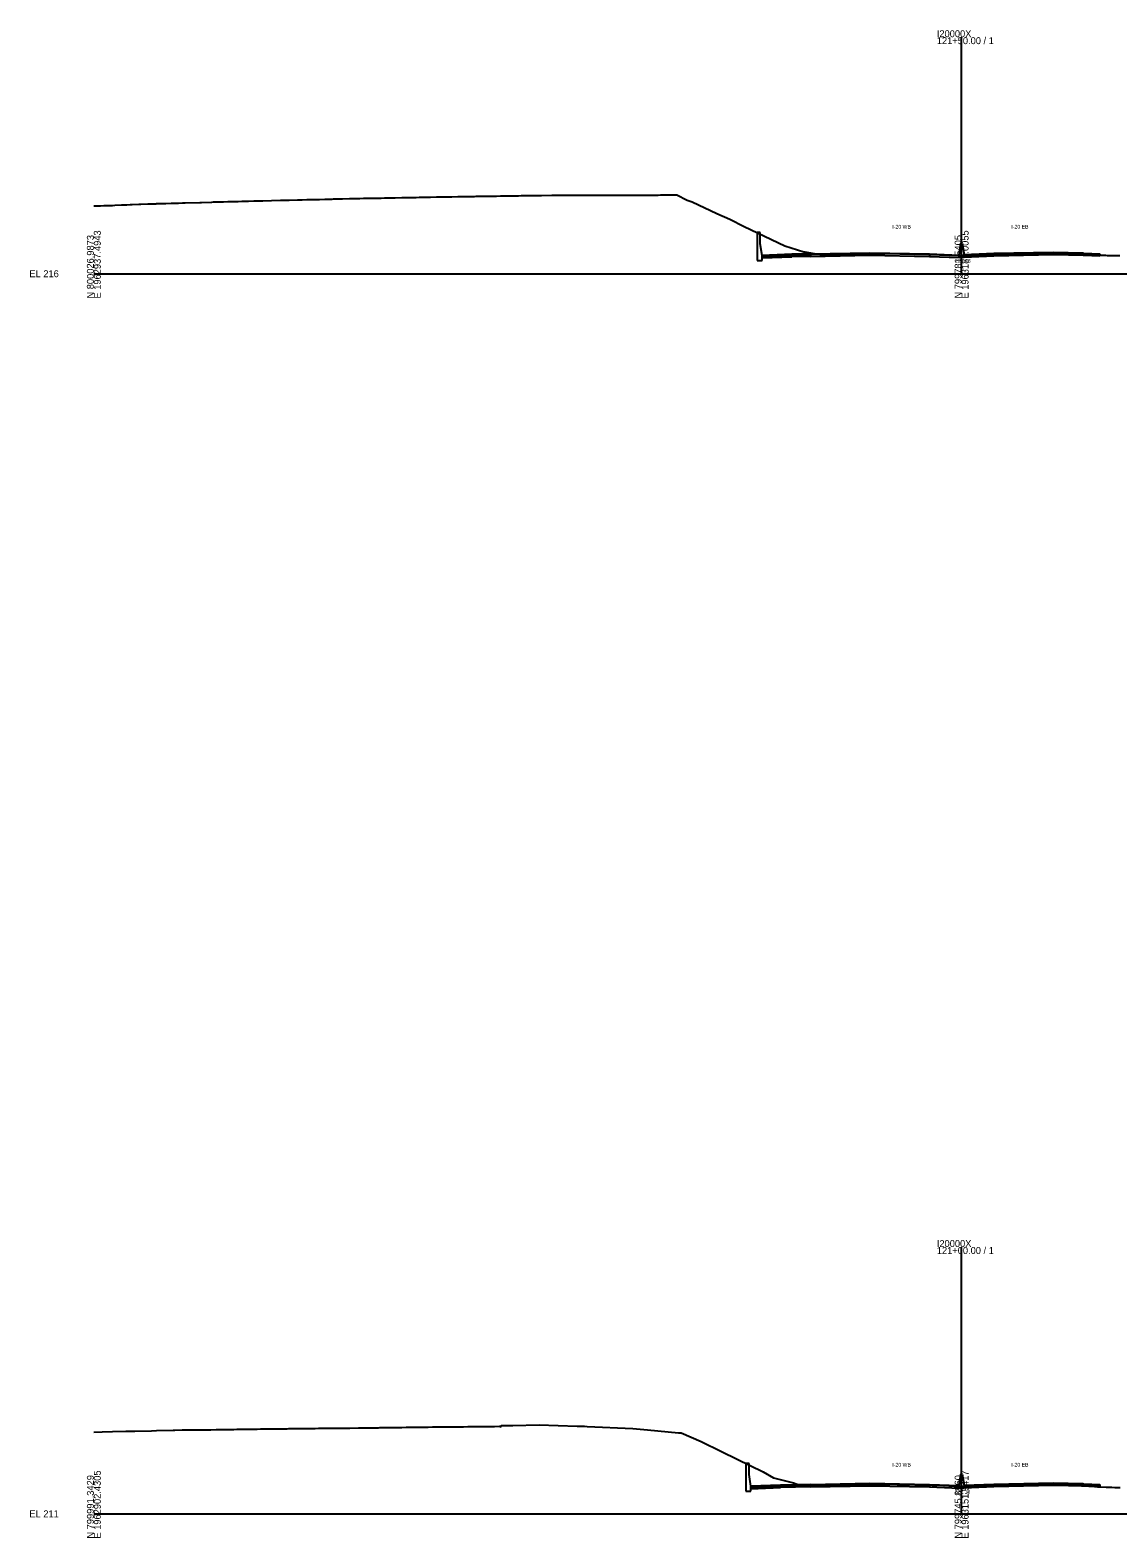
# Model space of a CAD drawing. Extents: x -4026 to 9638, y -10 to 19609.
# Drawn here: x 1974 to 2413, y 2490 to 3098 of the extents above; entities that cross this region are included whole.
import ezdxf

# ---------------------------------------------------------------- set-up
doc = ezdxf.new("R2010")
doc.units = 0
for name, color, linetype in [('Default', 7, 'Continuous'), ('RD_GPK_XS_Cell', 7, 'Continuous'), ('RD_TX_Misc1', 7, 'Continuous'), ('RD_XS_Base', 7, 'Continuous'), ('RD_XS_ExGround', 7, 'Continuous'), ('RD_XS_MedBWall', 7, 'Continuous'), ('RD_XS_Pave', 7, 'Continuous'), ('RD_XS_PaveOvlay', 7, 'Continuous'), ('RD_XS_TX_Elev_EX', 7, 'Continuous')]:
    doc.layers.add(name, color=color, linetype=linetype)

msp = doc.modelspace()

# ---------------------------------------------------------------- linework, layer by layer
at = {"layer": 'RD_GPK_XS_Cell'}
for p, q in [((2350, 3000), (2350, 3095.37)), ((2000, 3000), (2350, 3000)), ((2350, 3000), (2700, 3000)), ((2350, 2500), (2350, 2607.57)), ((2000, 2500), (2350, 2500)), ((2350, 2500), (2700, 2500))]:
    msp.add_line(p, q, dxfattribs=at)
at = {"layer": 'RD_XS_Base'}
for points in [[(2281.56, 3007.51), (2269.56, 3007.03)], [(2269.56, 3007.03), (2269.56, 3006.36)], [(2269.56, 3006.36), (2281.56, 3006.84)], [(2281.56, 3007.51), (2289, 3007.66)], [(2281.56, 3006.84), (2281.56, 3007.51)], [(2289, 3006.99), (2281.56, 3006.84)], [(2337, 3007.66), (2313, 3008.15), (2289, 3007.66)], [(2289, 3007.66), (2289, 3006.99)], [(2289, 3006.99), (2313, 3007.48), (2337, 3006.99)], [(2349, 3007.19), (2337, 3007.66)], [(2337, 3007.66), (2337, 3006.99)], [(2337, 3006.99), (2349, 3006.52)], [(2349, 3006.52), (2349, 3007.19)], [(2351, 3007.26), (2363, 3007.75)], [(2351, 3006.59), (2351, 3007.26)], [(2363, 3007.08), (2351, 3006.59)], [(2363, 3007.75), (2387, 3008.24), (2399, 3007.99)], [(2363, 3007.08), (2363, 3007.75)], [(2399, 3007.32), (2387, 3007.57), (2363, 3007.08)], [(2399, 3007.99), (2399.25, 3007.99)], [(2399, 3007.32), (2399, 3007.99)], [(2399.25, 3007.32), (2399, 3007.32)], [(2399.25, 3007.99), (2405.74, 3007.73)], [(2399.25, 3007.32), (2399.25, 3007.99)], [(2405.74, 3007.06), (2399.25, 3007.32)], [(2405.74, 3007.73), (2405.74, 3007.06)], [(2277, 2511.27), (2265, 2510.79)], [(2265, 2510.79), (2265, 2510.12)], [(2277, 2511.27), (2289, 2511.51)], [(2277, 2510.6), (2277, 2511.27)], [(2289, 2510.84), (2277, 2510.6)], [(2337, 2511.52), (2313, 2512), (2289, 2511.51)], [(2289, 2511.51), (2289, 2510.84)], [(2289, 2510.84), (2313, 2511.33), (2337, 2510.85)], [(2349, 2511.05), (2337, 2511.52)], [(2337, 2511.52), (2337, 2510.85)], [(2337, 2510.85), (2349, 2510.38)], [(2349, 2510.38), (2349, 2511.05)], [(2351, 2511.05), (2363, 2511.54)], [(2351, 2510.38), (2351, 2511.05)], [(2363, 2510.87), (2351, 2510.38)], [(2363, 2511.54), (2387, 2512.02), (2399, 2511.78)], [(2363, 2510.87), (2363, 2511.54)], [(2399, 2511.11), (2387, 2511.35), (2363, 2510.87)], [(2399, 2511.78), (2399.25, 2511.77)], [(2399, 2511.11), (2399, 2511.78)], [(2399.25, 2511.1), (2399, 2511.11)], [(2399.25, 2511.77), (2405.74, 2511.51)], [(2399.25, 2511.1), (2399.25, 2511.77)], [(2405.74, 2510.84), (2399.25, 2511.1)], [(2405.74, 2511.51), (2405.74, 2510.84)], [(2265, 2510.12), (2277, 2510.6)]]:
    msp.add_lwpolyline(points, dxfattribs=at)
at = {"layer": 'RD_XS_ExGround'}
for points in [[(2000, 3027.34), (2000.41, 3027.35), (2001.44, 3027.38), (2002.7, 3027.42), (2003.98, 3027.46), (2004.95, 3027.49), (2007.55, 3027.57), (2008.45, 3027.61), (2011.11, 3027.72), (2011.54, 3027.74), (2011.96, 3027.76), (2013.3, 3027.81), (2014.67, 3027.87), (2015.47, 3027.89), (2018.2, 3027.99), (2018.59, 3028.01), (2018.98, 3028.02), (2021.76, 3028.12), (2022.06, 3028.13), (2022.54, 3028.15), (2023.58, 3028.19), (2024.21, 3028.22), (2024.99, 3028.24), (2025.31, 3028.26), (2025.75, 3028.27), (2026.89, 3028.31), (2029.02, 3028.37), (2031.14, 3028.42), (2034.18, 3028.51), (2035.82, 3028.56), (2036.77, 3028.58), (2042.81, 3028.76), (2043.39, 3028.77), (2047.61, 3028.9), (2048.2, 3028.93), (2050.48, 3028.98), (2052.25, 3029.02), (2054.03, 3029.06), (2057.51, 3029.16), (2058.15, 3029.18), (2059.75, 3029.23), (2060.19, 3029.24), (2061.04, 3029.26), (2062.32, 3029.29), (2064.57, 3029.34), (2066.35, 3029.39), (2068.15, 3029.43), (2071.7, 3029.53), (2075.27, 3029.61), (2078.84, 3029.69), (2082.09, 3029.77), (2082.4, 3029.78), (2084, 3029.82), (2085.97, 3029.87), (2087.56, 3029.9), (2089.11, 3029.94), (2089.53, 3029.95), (2091.07, 3029.99), (2093.11, 3030.04), (2096.12, 3030.12), (2096.66, 3030.14), (2098.15, 3030.16), (2098.65, 3030.17), (2099.93, 3030.22), (2100.24, 3030.23), (2103.13, 3030.28), (2103.44, 3030.29), (2103.77, 3030.3), (2105.23, 3030.33), (2106.65, 3030.36), (2106.99, 3030.37), (2107.33, 3030.37), (2108.76, 3030.4), (2110.15, 3030.43), (2110.53, 3030.43), (2110.9, 3030.44), (2112.29, 3030.47), (2113.67, 3030.49), (2114.06, 3030.5), (2114.46, 3030.51), (2115.83, 3030.53), (2117.18, 3030.56), (2118.01, 3030.57), (2119.35, 3030.6), (2120.7, 3030.62), (2121.14, 3030.63), (2121.58, 3030.63), (2124.19, 3030.68), (2124.65, 3030.69), (2125.14, 3030.7), (2126.44, 3030.73), (2127.7, 3030.75), (2128.7, 3030.77), (2129.96, 3030.8), (2131.21, 3030.82), (2131.74, 3030.83), (2132.27, 3030.84), (2134.71, 3030.89), (2135.83, 3030.91), (2138.23, 3030.95), (2138.81, 3030.97), (2139.4, 3030.98), (2141.73, 3031.01), (2142.62, 3031.03), (2143.54, 3031.04), (2144.44, 3031.05), (2146.78, 3031.08), (2149.25, 3031.1), (2150.1, 3031.13), (2151.63, 3031.16), (2152.33, 3031.18), (2153.58, 3031.2), (2154.16, 3031.21), (2155.07, 3031.23), (2156.47, 3031.27), (2157.23, 3031.27), (2158.23, 3031.28), (2159.25, 3031.29), (2159.69, 3031.3), (2160.8, 3031.31), (2161.32, 3031.32), (2162.41, 3031.33), (2164.06, 3031.35), (2165.5, 3031.37), (2167.4, 3031.4), (2167.94, 3031.41), (2168.6, 3031.42), (2170.61, 3031.45), (2171.03, 3031.46), (2171.34, 3031.46), (2172.42, 3031.48), (2173.25, 3031.49), (2174.86, 3031.51), (2175.74, 3031.52), (2180.52, 3031.58), (2184.69, 3031.64), (2185.88, 3031.66), (2188.16, 3031.69), (2189.14, 3031.66), (2189.86, 3031.64), (2190.28, 3031.63), (2191.87, 3031.63), (2192.88, 3031.63), (2194.32, 3031.64), (2194.87, 3031.65), (2196.48, 3031.64), (2197.8, 3031.65), (2198.9, 3031.67), (2200.05, 3031.67), (2200.71, 3031.68), (2201.31, 3031.69), (2203.62, 3031.72), (2204.23, 3031.73), (2204.82, 3031.73), (2207.15, 3031.73), (2208.33, 3031.72), (2209.53, 3031.72), (2210.74, 3031.73), (2211.83, 3031.73), (2214.3, 3031.74), (2215.35, 3031.74), (2216.59, 3031.74), (2217.88, 3031.73), (2218.36, 3031.73), (2218.85, 3031.73), (2220.12, 3031.73), (2221.6, 3031.73), (2222.42, 3031.73), (2223.17, 3031.73), (2224.39, 3031.73), (2224.77, 3031.73), (2225.66, 3031.74), (2227.55, 3031.74), (2228.58, 3031.75), (2229.38, 3031.75), (2230.48, 3031.76), (2232.13, 3031.77), (2232.89, 3031.78), (2234.45, 3031.79), (2235.09, 3031.78), (2239.37, 3029.62), (2241.35, 3028.93), (2251.26, 3024.32), (2256.46, 3021.94), (2262.34, 3019.08), (2278.72, 3011.26), (2286.39, 3008.86), (2286.73, 3008.8), (2292.8, 3007.8), (2294.17, 3007.72), (2294.47, 3007.7), (2294.93, 3007.66), (2295.74, 3007.61), (2297.36, 3007.51), (2298.13, 3007.56), (2298.49, 3007.58), (2299.18, 3007.68), (2299.83, 3007.75), (2303.43, 3007.88), (2306.33, 3007.98), (2306.77, 3007.99), (2307.34, 3008.02), (2307.76, 3008.03), (2310.04, 3008.09), (2310.56, 3008.1), (2314.11, 3008.16), (2316.92, 3008.2), (2317.29, 3008.2), (2317.65, 3008.21), (2318.39, 3008.21), (2319.21, 3008.21), (2320.09, 3008.2), (2321.18, 3008.19), (2322.68, 3008.16), (2323.96, 3008.13), (2324.8, 3008.12), (2327.77, 3008.04), (2328.39, 3008.03), (2330.95, 3007.96), (2331.95, 3007.95), (2334.75, 3007.9), (2335.5, 3007.88), (2337.93, 3007.82), (2339.05, 3007.79), (2341.73, 3007.73), (2342.29, 3007.72), (2342.81, 3007.7), (2343.21, 3007.68), (2344.34, 3007.59), (2344.76, 3007.56), (2345.12, 3007.53), (2345.43, 3007.51), (2346.03, 3007.49), (2346.9, 3007.44), (2349.13, 3007.44), (2350, 3007.43), (2352.85, 3007.42), (2353.61, 3007.46), (2354.55, 3007.52), (2354.84, 3007.54), (2355.72, 3007.65), (2356.46, 3007.73), (2356.91, 3007.76), (2357.23, 3007.76), (2359.16, 3007.79), (2360.45, 3007.82), (2362.52, 3007.86), (2364, 3007.89), (2366.2, 3007.93), (2367.56, 3007.96), (2368.6, 3007.98), (2369.78, 3008.02), (2370.46, 3008.04), (2371.11, 3008.06), (2372.97, 3008.11), (2374.7, 3008.16), (2376.64, 3008.19), (2378.3, 3008.22), (2379.52, 3008.24), (2380.61, 3008.22), (2381.09, 3008.21), (2381.85, 3008.2), (2383.84, 3008.16), (2385.42, 3008.12), (2387.24, 3008.07), (2388.97, 3008.02), (2390.6, 3007.97), (2392.51, 3007.88), (2393.3, 3007.84), (2394.19, 3007.82), (2395.18, 3007.8), (2396.08, 3007.77), (2397.79, 3007.71), (2399.65, 3007.65), (2401.1, 3007.6), (2403.23, 3007.53), (2403.96, 3007.5), (2404.71, 3007.47), (2405.77, 3007.43), (2406.77, 3007.43), (2408.05, 3007.42), (2408.66, 3007.41), (2410.35, 3007.39), (2411.69, 3007.37), (2413.87, 3007.34)], [(2000, 2532.95), (2003.34, 2533.03), (2007.51, 2533.13), (2012.96, 2533.26), (2016.56, 2533.34), (2023.25, 2533.5), (2025.26, 2533.55), (2032.06, 2533.72), (2032.63, 2533.73), (2035.63, 2533.8), (2037.33, 2533.81), (2037.75, 2533.81), (2038.81, 2533.82), (2039.43, 2533.83), (2040.03, 2533.84), (2040.62, 2533.84), (2042.28, 2533.86), (2043.6, 2533.88), (2044.74, 2533.89), (2045.83, 2533.9), (2047.13, 2533.92), (2049.39, 2533.95), (2050, 2533.96), (2050.62, 2533.96), (2052.95, 2533.99), (2054.11, 2534.01), (2055.31, 2534.03), (2056.52, 2534.05), (2057.65, 2534.06), (2060.11, 2534.1), (2060.63, 2534.1), (2061.14, 2534.11), (2063.67, 2534.14), (2064.62, 2534.16), (2065.93, 2534.18), (2067.22, 2534.2), (2067.82, 2534.2), (2068.73, 2534.22), (2070.25, 2534.23), (2071.01, 2534.25), (2073.21, 2534.27), (2074.37, 2534.28), (2074.76, 2534.29), (2075.15, 2534.29), (2075.72, 2534.3), (2077.91, 2534.32), (2078.68, 2534.33), (2080.06, 2534.35), (2081.46, 2534.36), (2081.84, 2534.36), (2082.2, 2534.37), (2085.04, 2534.39), (2085.37, 2534.4), (2085.69, 2534.4), (2088.59, 2534.44), (2088.9, 2534.44), (2089.2, 2534.45), (2090.67, 2534.47), (2092.69, 2534.48), (2094.21, 2534.5), (2095.71, 2534.51), (2096.24, 2534.51), (2097.74, 2534.53), (2099.25, 2534.54), (2099.75, 2534.55), (2101.27, 2534.57), (2103.25, 2534.59), (2106.75, 2534.63), (2110.27, 2534.67), (2113.77, 2534.71), (2114.86, 2534.73), (2115.41, 2534.74), (2117.28, 2534.76), (2118.96, 2534.79), (2120.77, 2534.82), (2122.49, 2534.84), (2124.27, 2534.86), (2126.02, 2534.89), (2127.79, 2534.91), (2131.36, 2534.96), (2133.09, 2534.98), (2134.89, 2535), (2136.63, 2535.02), (2138.49, 2535.04), (2142.01, 2535.07), (2143.69, 2535.08), (2145.31, 2535.09), (2145.66, 2535.1), (2149.16, 2535.12), (2150.78, 2535.14), (2152.35, 2535.16), (2152.78, 2535.17), (2154.23, 2535.17), (2155.87, 2535.2), (2156.28, 2535.2), (2157.64, 2535.2), (2158.87, 2535.2), (2160.18, 2535.24), (2161.57, 2535.26), (2163.45, 2535.28), (2163.83, 2535.15), (2164.15, 2535.1), (2164.47, 2535.55), (2166.35, 2535.6), (2168.96, 2535.66), (2179.63, 2535.86), (2194.89, 2535.39), (2197.96, 2535.27), (2198.95, 2535.21), (2217.35, 2534.33), (2223.35, 2533.88), (2235.85, 2532.68), (2236.86, 2532.59), (2244.92, 2529.1), (2253.11, 2525.18), (2259.46, 2522.02), (2269.97, 2516.9), (2274.09, 2514.47), (2282.16, 2512.47), (2285.1, 2511.47), (2286.71, 2511.21), (2292.7, 2511.32), (2294.75, 2511.15), (2298.08, 2511.22), (2298.25, 2511.34), (2298.53, 2511.34), (2299.29, 2511.45), (2299.61, 2511.47), (2301.07, 2511.53), (2302.54, 2511.59), (2303.1, 2511.61), (2304.62, 2511.65), (2306.07, 2511.7), (2306.8, 2511.73), (2307.51, 2511.76), (2309.94, 2511.82), (2313.7, 2511.9), (2316.73, 2511.94), (2317.15, 2511.94), (2319.39, 2511.95), (2320.64, 2511.94), (2322.28, 2511.91), (2324.06, 2511.87), (2325.74, 2511.83), (2327.46, 2511.79), (2327.91, 2511.78), (2331.11, 2511.71), (2334.63, 2511.66), (2336.43, 2511.63), (2338.13, 2511.58), (2338.73, 2511.57), (2341.67, 2511.51), (2342.83, 2511.48), (2344.8, 2511.31), (2345.13, 2511.27), (2346.99, 2511.19), (2347.41, 2511.2), (2347.92, 2511.2), (2350, 2511.16), (2351.23, 2511.13), (2351.76, 2511.12), (2352.22, 2511.11), (2352.57, 2511.12), (2354.69, 2511.21), (2355.01, 2511.23), (2355.95, 2511.4), (2357.16, 2511.47), (2359.61, 2511.5), (2361.17, 2511.53), (2362.57, 2511.56), (2363.09, 2511.57), (2366.23, 2511.62), (2366.64, 2511.63), (2370.2, 2511.72), (2371.69, 2511.77), (2373.77, 2511.82), (2375.26, 2511.86), (2376.73, 2511.89), (2377.43, 2511.9), (2379.19, 2511.94), (2379.51, 2511.95), (2380.45, 2511.94), (2380.97, 2511.93), (2382.34, 2511.91), (2384.51, 2511.86), (2387.7, 2511.77), (2388.04, 2511.76), (2390.83, 2511.67), (2391.43, 2511.64), (2391.86, 2511.62), (2392.53, 2511.58), (2394.3, 2511.52), (2394.72, 2511.51), (2395.16, 2511.48), (2396.52, 2511.42), (2397.85, 2511.35), (2398.31, 2511.33), (2398.78, 2511.3), (2400.08, 2511.22), (2401.35, 2511.14), (2402.34, 2511.09), (2404.82, 2510.93), (2405.87, 2510.87), (2408.31, 2510.78), (2408.85, 2510.77), (2409.4, 2510.75), (2410.62, 2510.7), (2411.78, 2510.66), (2412.38, 2510.64), (2413.01, 2510.62), (2413.96, 2510.59)]]:
    msp.add_lwpolyline(points, dxfattribs=at)
at = {"layer": 'RD_XS_MedBWall'}
for points in [[(2268.81, 3016.59), (2267.56, 3016.59)], [(2267.56, 3016.59), (2267.56, 3005.37)], [(2268.81, 3012.04), (2268.81, 3016.59)], [(2269.56, 3007.37), (2268.81, 3012.04)], [(2349, 3007.52), (2349.75, 3012.26), (2350.25, 3012.26), (2351, 3007.59)], [(2267.56, 3005.37), (2269.56, 3005.37)], [(2269.56, 3005.37), (2269.56, 3007.37)], [(2349, 3006.52), (2349, 3007.52)], [(2351, 3006.52), (2349, 3006.52)], [(2351, 3007.59), (2351, 3006.52)], [(2264.25, 2520.29), (2263, 2520.29)], [(2263, 2520.29), (2263, 2509.13)], [(2264.25, 2515.8), (2264.25, 2520.29)], [(2265, 2511.13), (2264.25, 2515.8)], [(2265, 2509.13), (2265, 2511.13)], [(2349, 2511.37), (2349.75, 2516.04), (2350.25, 2516.04), (2351, 2511.37)], [(2349, 2510.37), (2349, 2511.37)], [(2351, 2511.37), (2351, 2510.37)], [(2263, 2509.13), (2265, 2509.13)], [(2351, 2510.37), (2349, 2510.37)]]:
    msp.add_lwpolyline(points, dxfattribs=at)
at = {"layer": 'RD_XS_Pave'}
for points in [[(2281.56, 3007.68), (2269.56, 3007.2)], [(2269.56, 3007.03), (2281.56, 3007.51)], [(2269.56, 3007.2), (2269.56, 3007.03)], [(2281.56, 3007.68), (2289, 3007.83)], [(2281.56, 3007.51), (2281.56, 3007.68)], [(2289, 3007.66), (2281.56, 3007.51)], [(2289, 3007.83), (2313, 3008.31), (2337, 3007.83)], [(2337, 3007.66), (2313, 3008.15), (2289, 3007.66)], [(2289, 3007.83), (2289, 3007.66)], [(2337, 3007.83), (2337, 3007.66)], [(2337, 3007.83), (2349, 3007.36)], [(2349, 3007.19), (2337, 3007.66)], [(2349, 3007.36), (2349, 3007.19)], [(2363, 3007.92), (2351, 3007.43)], [(2351, 3007.26), (2363, 3007.75)], [(2351, 3007.43), (2351, 3007.26)], [(2399, 3008.16), (2387, 3008.4), (2363, 3007.92)], [(2363, 3007.75), (2387, 3008.24), (2399, 3007.99)], [(2363, 3007.92), (2363, 3007.75)], [(2399, 3008.16), (2399.25, 3008.16)], [(2399, 3007.99), (2399, 3008.16)], [(2399.25, 3007.99), (2399, 3007.99)], [(2399.25, 3008.16), (2399.25, 3007.99)], [(2399.25, 3008.16), (2405.74, 3007.9)], [(2405.74, 3007.73), (2399.25, 3007.99)], [(2405.74, 3007.9), (2405.74, 3007.73)], [(2277, 2511.44), (2265, 2510.96)], [(2265, 2510.79), (2277, 2511.27)], [(2265, 2510.96), (2265, 2510.79)], [(2277, 2511.44), (2289, 2511.68)], [(2289, 2511.51), (2277, 2511.27)], [(2277, 2511.27), (2277, 2511.44)], [(2289, 2511.68), (2313, 2512.17), (2337, 2511.69)], [(2337, 2511.52), (2313, 2512), (2289, 2511.51)], [(2289, 2511.68), (2289, 2511.51)], [(2337, 2511.69), (2337, 2511.52)], [(2337, 2511.69), (2349, 2511.22)], [(2349, 2511.05), (2337, 2511.52)], [(2349, 2511.22), (2349, 2511.05)], [(2363, 2511.71), (2351, 2511.22)], [(2351, 2511.05), (2363, 2511.54)], [(2351, 2511.22), (2351, 2511.05)], [(2399, 2511.95), (2387, 2512.19), (2363, 2511.71)], [(2363, 2511.54), (2387, 2512.02), (2399, 2511.78)], [(2363, 2511.71), (2363, 2511.54)], [(2399, 2511.95), (2399.25, 2511.94)], [(2399, 2511.78), (2399, 2511.95)], [(2399.25, 2511.77), (2399, 2511.78)], [(2399.25, 2511.94), (2399.25, 2511.77)], [(2399.25, 2511.94), (2405.74, 2511.68)], [(2405.74, 2511.51), (2399.25, 2511.77)], [(2405.74, 2511.68), (2405.74, 2511.51)]]:
    msp.add_lwpolyline(points, dxfattribs=at)
at = {"layer": 'RD_XS_PaveOvlay'}
for points in [[(2281.56, 3007.85), (2269.56, 3007.37)], [(2269.56, 3007.2), (2281.56, 3007.68)], [(2269.56, 3007.37), (2269.56, 3007.2)], [(2289, 3008), (2281.56, 3007.85)], [(2281.56, 3007.85), (2281.56, 3007.68)], [(2281.56, 3007.68), (2289, 3007.83)], [(2289, 3008), (2313, 3008.48), (2337, 3008)], [(2337, 3007.83), (2313, 3008.31), (2289, 3007.83)], [(2289, 3007.83), (2289, 3008)], [(2337, 3008), (2337, 3007.83)], [(2337, 3008), (2349, 3007.52)], [(2349, 3007.36), (2337, 3007.83)], [(2349, 3007.52), (2349, 3007.36)], [(2363, 3008.09), (2351, 3007.59)], [(2351, 3007.43), (2363, 3007.92)], [(2351, 3007.59), (2351, 3007.43)], [(2399, 3008.33), (2387, 3008.57), (2363, 3008.09)], [(2363, 3007.92), (2387, 3008.4), (2399, 3008.16)], [(2363, 3008.09), (2363, 3007.92)], [(2399, 3008.16), (2399, 3008.33)], [(2399, 3008.33), (2399.25, 3008.32)], [(2399.25, 3008.16), (2399, 3008.16)], [(2399.25, 3008.32), (2405.74, 3008.06)], [(2399.25, 3008.16), (2399.25, 3008.32)], [(2405.74, 3007.9), (2399.25, 3008.16)], [(2405.74, 3008.06), (2405.74, 3007.9)], [(2277, 2511.61), (2265, 2511.13)], [(2265, 2510.96), (2277, 2511.44)], [(2265, 2511.13), (2265, 2510.96)], [(2289, 2511.85), (2277, 2511.61)], [(2277, 2511.44), (2289, 2511.68)], [(2277, 2511.61), (2277, 2511.44)], [(2289, 2511.85), (2313, 2512.33), (2337, 2511.85)], [(2337, 2511.69), (2313, 2512.17), (2289, 2511.68)], [(2289, 2511.68), (2289, 2511.85)], [(2337, 2511.85), (2337, 2511.69)], [(2337, 2511.85), (2349, 2511.37)], [(2349, 2511.22), (2337, 2511.69)], [(2349, 2511.37), (2349, 2511.22)], [(2363, 2511.88), (2351, 2511.37)], [(2351, 2511.22), (2363, 2511.71)], [(2351, 2511.37), (2351, 2511.22)], [(2399, 2512.12), (2387, 2512.36), (2363, 2511.88)], [(2363, 2511.71), (2387, 2512.19), (2399, 2511.95)], [(2363, 2511.88), (2363, 2511.71)], [(2399, 2511.95), (2399, 2512.12)], [(2399, 2512.12), (2399.25, 2512.11)], [(2399.25, 2511.94), (2399, 2511.95)], [(2399.25, 2512.11), (2405.74, 2511.85)], [(2399.25, 2511.94), (2399.25, 2512.11)], [(2405.74, 2511.68), (2399.25, 2511.94)], [(2405.74, 2511.85), (2405.74, 2511.68)]]:
    msp.add_lwpolyline(points, dxfattribs=at)

# ---------------------------------------------------------------- texts
at = {"layer": 'Default'}
for p in [(2000, 3000), (2000, 2500)]:
    msp.add_text('-', height=0.0001, dxfattribs=at).set_placement(p)
at = {"layer": 'RD_GPK_XS_Cell'}
for s, p in [('121+50.00 / 1', (2340, 3092.57)), ('I20000X', (2340, 3095.37)), ('EL 216', (1974, 2998.6)), ('I20000X', (2340, 2607.57)), ('121+00.00 / 1', (2340, 2604.77)), ('EL 211', (1974, 2498.6))]:
    msp.add_text(s, height=2.8, dxfattribs=at).set_placement(p)
for s, p in [('N 800026.9873', (2000, 2990)), ('E 1962937.4943', (2002.8, 2990)), ('N 799781.5405', (2350, 2990)), ('E 1963187.0055', (2352.8, 2990)), ('E 1962902.4305', (2002.8, 2490)), ('E 1963151.9417', (2352.8, 2490)), ('N 799991.3429', (2000, 2490)), ('N 799745.8960', (2350, 2490))]:
    msp.add_text(s, height=2.8, rotation=90, dxfattribs=at).set_placement(p)
at = {"layer": 'RD_TX_Misc1'}
for s, p in [('I-20 WB', (2322.06, 3018.21)), ('I-20 EB', (2370.06, 3018.21)), ('I-20 WB', (2322.06, 2519.05)), ('I-20 EB', (2370.06, 2519.05))]:
    msp.add_text(s, height=1.5, dxfattribs=at).set_placement(p)
at = {"layer": 'RD_XS_TX_Elev_EX'}
for s, p in [('223.43', (2347.31, 3004.43)), ('222.16', (2347.18, 2508.16))]:
    msp.add_text(s, height=1.5, dxfattribs=at).set_placement(p)

doc.saveas('drawing.dxf')
